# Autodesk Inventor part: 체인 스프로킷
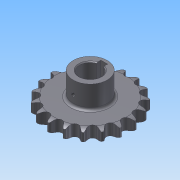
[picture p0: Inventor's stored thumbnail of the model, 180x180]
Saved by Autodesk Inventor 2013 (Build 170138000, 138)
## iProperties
Created: 2014-07
Part Number: 체인 스프로킷
Material: 강철
Document SubType Name: Modeling
Designer: KYOUNG IL JANG
Density: 7.85 g/cm^3
Mass: 738.6 g
Surface Area: 236.854 cm^2
Volume: 94.0892 cm^3
CustomPartVersion: 1
Company: 한국ATC센터
Author: KYOUNG IL JANG
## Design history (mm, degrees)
sketch "이론적 톱니 프로파일"
  geometry: L1 (0, 0)-(0, 45.567); L2 (0, 0)-(14.795, 43.098); L3 (0, 45.567)-(14.795, 43.098); L4 (0, 45.567)-(5.661, 50.015); L5 (5.661, 50.015)-(-5.141, 45.406); L6 (-12.428, 43.493)-(-5.573, 46.417); L7 (-5.141, 45.406)-(-5.573, 46.417); L8 (5.573, 46.417)-(5.141, 45.406); L9 (0, 0)-(8.138, 48.771); A1 r 45.567 centre (0, 0) between (0, 45.567) and (14.795, 43.098); A2 r 49.445 centre (0, 0) between (7.302, 48.903) and (-7.302, 48.903); A3 r 4.545 centre (0, 45.567) between (-3.574, 42.758) and (3.574, 42.758); A4 r 7.453 centre (12.428, 43.493) between (7.302, 48.903) and (5.573, 46.417); A5 r 7.453 centre (-12.428, 43.493) between (-5.573, 46.417) and (-7.302, 48.903); A6 r 11.745 centre (5.661, 50.015) between (-5.141, 45.406) and (-3.574, 42.758); A7 r 11.745 centre (-5.661, 50.015) between (3.574, 42.758) and (5.141, 45.406); 2 further points
  constraints: 18 end point, 15 point on circle, 7 centre point, 3 coincident, 3 point on line, 3 symmetric about line, 3 tangent, 1 equal radius, 1 midpoint, 1 parallel, 1 vertical, 1 other
  dimensions: "d0" = 91.13301 diameter of A1 (computed from da_p, da_z); "d2" = 18.9474 deg angle of L2 L1 (computed from da_z); "d3" = 4.545 radius of A3 (= 0.5 x da_Dr + da_SC); "d10" = 128.158 deg angle of L4 L1 (computed from da_z); "d11" = 15.0526 deg angle of L5 L4 (computed from da_z); "d12" = 7.2 distance of L3.start L4.end (= 0.8 x da_Dr); "d13" = 11.745 distance of L4.end L5.end (= 1.3 x da_Dr + da_SC); "d14" = 12.6 distance of A4.centre L1.end (= 1.4 x da_Dr); "d23" = 4.5 distance from line of L9.end L3 (= da_Ha)
sketch "톱니 프로파일"
  geometry: L1 (0, 0)-(0, 45.567); L2 (0, 45.567)-(4.203, 43.837); L3 (0, 45.567)-(-4.203, 43.837); A1 r 4.545 centre (0, 45.567) between (-4.203, 43.837) and (4.203, 43.837); A2 r 22.68 centre (25.176, 35.206) between (7.12, 48.93) and (4.203, 43.837); A3 r 22.68 centre (-25.176, 35.206) between (-4.203, 43.837) and (-7.12, 48.93); A4 r 49.445 centre (0, 0) between (-7.12, 48.93) and (7.12, 48.93) reference; 1 further point
  constraints: 9 point on circle, 6 end point, 3 centre point, 2 tangent, 1 coincident, 1 equal radius, 1 vertical, 1 other
  dimensions: "d44" = 135.263 deg angle of L3 L2 (= da_Alfa); "d45" = 22.68 radius of A2 (= da_Re); "d46" = 4.545 radius of A1 (= da_Ri)
sketch "단면 프로파일"
  geometry: L1 (49.445, 0)-(-49.445, 0) reference; L2 (33.265, 6.65)-(-33.265, 6.65); L3 (-33.265, 6.65)-(-33.265, -6.65); L4 (-33.265, -6.65)-(33.265, -6.65); L5 (33.265, -6.65)-(33.265, 6.65); L6 (33.265, 6.65)-(49.445, 6.65); L7 (49.445, 6.65)-(49.445, -6.65); L8 (49.445, -6.65)-(33.265, -6.65); L9 (33.265, -6.65)-(33.265, 6.65); L10 (42.183, 6.65)-(0, 6.65); L11 (0, 6.65)-(0, -6.65); L12 (0, -6.65)-(42.183, -6.65); L13 (0, 6.65)-(0, -6.65); L14 (49.445, 4.775)-(49.445, -4.775); A1 r 15 centre (42.183, -8.35) between (49.445, 4.775) and (42.183, 6.65); A2 r 15 centre (42.183, 8.35) between (42.183, -6.65) and (49.445, -4.775); 2 further points
  constraints: 26 end point, 7 midpoint, 5 perpendicular, 4 parallel, 4 point on circle, 3 point on line, 3 symmetric about line, 2 centre point, 2 horizontal, 2 tangent, 1 collinear, 1 other
  dimensions: "d30" = 13.3 distance between parallel lines of L8 L6 (= da_Bf); "d31" = 66.53007 distance between parallel lines of L3 L5 (= da_Ds); "d32" = 13.3 distance between parallel lines of L4 L2 (= da_Bs); "d33" = 1.875 distance from line of L14.start L6 (= da_Ba); "d34" = 15 radius of A1 (= da_Rx); "d43" = 6.65 distance between parallel lines of L4 L1 (computed from da_k, da_pt, da_Bs)
revolve "슈라우드" stored, may be unused: angle "d36" = 90 deg
revolve "스트랜드" stored, may be unused: angle "d37" = 90 deg
extrude "이론적 톱니" cut sketch "이론적 톱니 프로파일" stored distance "d18" = 10; taper "d19" = 0 deg; dims "d49" = 0, "form_type" = 0 [user parameter]
extrude "톱니" cut sketch "톱니 프로파일" stored distance "d47" = 10; taper "d48" = 0 deg; dims "d50" = 10, "form_type" = 0 [user parameter]
node "타이밍 평면"
node "작업 평면3"
sketch "스케치5"
  geometry: C1 r 20 at (0, -45.567); 1 further point
  constraints: 1 centre point, 1 coincident
  dimensions: "d52" = 40 diameter of C1
extrude "돌출4" join sketch "스케치5" stored distance "d53" = 10; taper "d54" = 0 deg
sketch "스케치6"
  geometry: L1 (4, 11.843)-(4, 16.5); L2 (4, 16.5)-(-4, 16.5); L3 (-4, 16.5)-(-4, 11.843); A1 r 12.5 centre (0, 0) between (4, 11.843) and (-4, 11.843); 1 further point
  constraints: 6 end point, 2 parallel, 2 point on circle, 1 centre point, 1 coincident, 1 perpendicular, 1 vertical
  dimensions: "d55" = 25 diameter of A1; "d56" = 29 dimension on A1 L2 (computed from d55); "d57" = 8 distance of L1.end L2.end
extrude "돌출5" cut sketch "스케치6" stored distance "d58" = 10; taper "d59" = 0 deg
fillet "모깎기2" dims "d60" = 3
chamfer "모따기1" distance "d61" = 1; stored, may be unused: second distance "d62" = 2, angle "d63" = 45 deg
node "작업 평면4"
sketch "스케치7"
  geometry: L1 (-13.5, -13.3)-(13.5, -13.3) reference; 4 further points
  constraints: 1 vertical alignment
  dimensions: "d65" = 25 distance from line of point (0, 11.7) L1
hole "구멍1" sketch "스케치7" at (0, 11.7) diameter "d66" = 4.134; stored, may be unused: countersink angle "d70" = 90 deg, drill point angle "d72" = 118 deg; dims "d67" = 6, "d68" = 4, "d69" = 2, "d71" = 8
body "Solid1"
pattern_linear "스트랜드 패턴" dims "d40" = 24 (= da_pt)
pattern_circular "톱니 패턴" dims angle "d21" = 360 deg
other parameters: "da_p" = 15 [user parameter; used in 1 equation term], "da_Dr" = 9 [user parameter; used in 4 equation terms], "da_SC" = 0.045 [user parameter; used in 2 equation terms], "da_Ha" = 4.5 [user parameter; used in 1 equation term], "da_pt" = 24 [user parameter; used in 2 equation terms], "da_Bf" = 13.3 [user parameter; used in 1 equation term], "d28" = 0, "d29" = 0, "da_Ba" = 1.875 [user parameter; used in 1 equation term], "da_Rx" = 15 [user parameter; used in 1 equation term], "da_Ra" = 0.6 [user parameter], "da_Bs" = 13.3 [user parameter; used in 2 equation terms], "da_Ds" = 66.53007 [user parameter; used in 1 equation term], "d42" = 0, "da_Re" = 22.68 [user parameter; used in 1 equation term], "da_Ri" = 4.545 [user parameter; used in 1 equation term], "da_Alfa" = 135.263 deg [user parameter; used in 1 equation term]
